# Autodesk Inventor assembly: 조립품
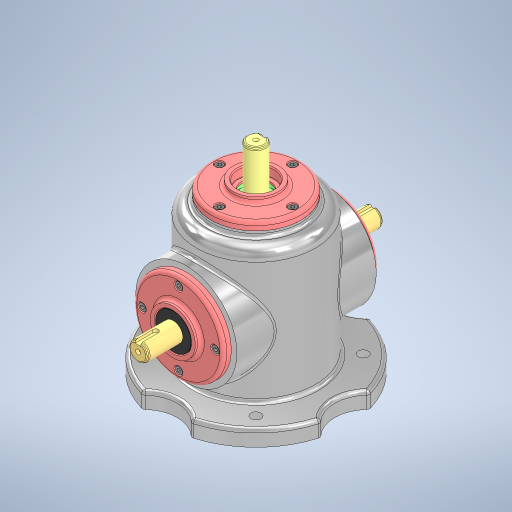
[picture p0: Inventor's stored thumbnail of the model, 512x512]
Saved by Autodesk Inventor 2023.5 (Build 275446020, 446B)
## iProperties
Created: 2026-07
Part Number: 조립품
Document SubType Name: Assembly
Designer: mirae
Author: mirae
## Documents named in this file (12)
- C:\Users\mirae\Desktop\760703V1006\조립품.iam
- C:\Users\mirae\Desktop\760703V1006\본체.ipt
- C:\Users\mirae\Desktop\760703V1006\6각 구멍붙이 볼트 M4x10\6각 구멍붙이 볼트 M4x10.ipt
- C:\Users\mirae\Desktop\760703V1006\깊은 홈 볼 베어링 6203\깊은 홈 볼 베어링 6203.ipt
- C:\Users\mirae\Desktop\760703V1006\메인 베벨기어\메인 베벨기어.ipt
- C:\Users\mirae\Desktop\760703V1006\메인 축\메인 축.ipt
- C:\Users\mirae\Desktop\760703V1006\서브 베벨기어\서브 베벨기어.ipt
- C:\Users\mirae\Desktop\760703V1006\서브 축\서브 축.ipt
- C:\Users\mirae\Desktop\760703V1006\오일 실 17 32 8\오일 실 17 32 8.ipt
- C:\Users\mirae\Desktop\760703V1006\커버\커버.ipt
- C:\Users\mirae\Desktop\760703V1006\평행 키 4x4x14\평행 키 4x4x14.ipt
- C:\Users\mirae\Desktop\760703V1006\평행 키 5x5x14\평행 키 5x5x14.ipt
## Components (12 placed, 1 different names)
1. 6각 구멍붙이 볼트 M4x10:1 — 각도:10
2. 6각 구멍붙이 볼트 M4x10:3
3. 6각 구멍붙이 볼트 M4x10:4
4. 6각 구멍붙이 볼트 M4x10:5
5. 6각 구멍붙이 볼트 M4x10:2 — 각도:11
6. 6각 구멍붙이 볼트 M4x10:7
7. 6각 구멍붙이 볼트 M4x10:8
8. 6각 구멍붙이 볼트 M4x10:9
9. 6각 구멍붙이 볼트 M4x10:6 — 각도:12
10. 6각 구멍붙이 볼트 M4x10:10
11. 6각 구멍붙이 볼트 M4x10:11
12. 6각 구멍붙이 볼트 M4x10:12
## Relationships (3: Angle 3)
- 각도:10 [Angle]: 6각 구멍붙이 볼트 M4x10:1
- 각도:11 [Angle]: 6각 구멍붙이 볼트 M4x10:2
- 각도:12 [Angle]: 6각 구멍붙이 볼트 M4x10:6
